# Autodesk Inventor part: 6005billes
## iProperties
Shininess: 64.0
Length Units: 11269
Angle Units: 11279
Time Units: 11290
Mass Units: 11283
Length Display Precision: 3
Angle Display Precision: 2
Compacted: True
Part Number: 6005billes
Document SubType Name: Modeling
Created: 2004-09
Material: Par défaut
Density: 1 g/cm^3
Density: 0.0
Volumn: 0.0
Area: 0.0
PropertySet Name: Model Information
Control State: 0
Master: False
Checked Out: False
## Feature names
1. Révolution1 [Revolution]
